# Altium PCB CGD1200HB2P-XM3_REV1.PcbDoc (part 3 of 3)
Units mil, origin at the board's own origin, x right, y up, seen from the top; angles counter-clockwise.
Board outline 2086.61 x 3149.61 mil, 6 copper layers (TOP, LAYER2, LAYER3, LAYER4, LAYER5, BOTTOM), stack 57.2 mil thick; 178 components, 101 nets, 513 pads, 419 vias.
Unrouted connection lines stored in the file: 206.
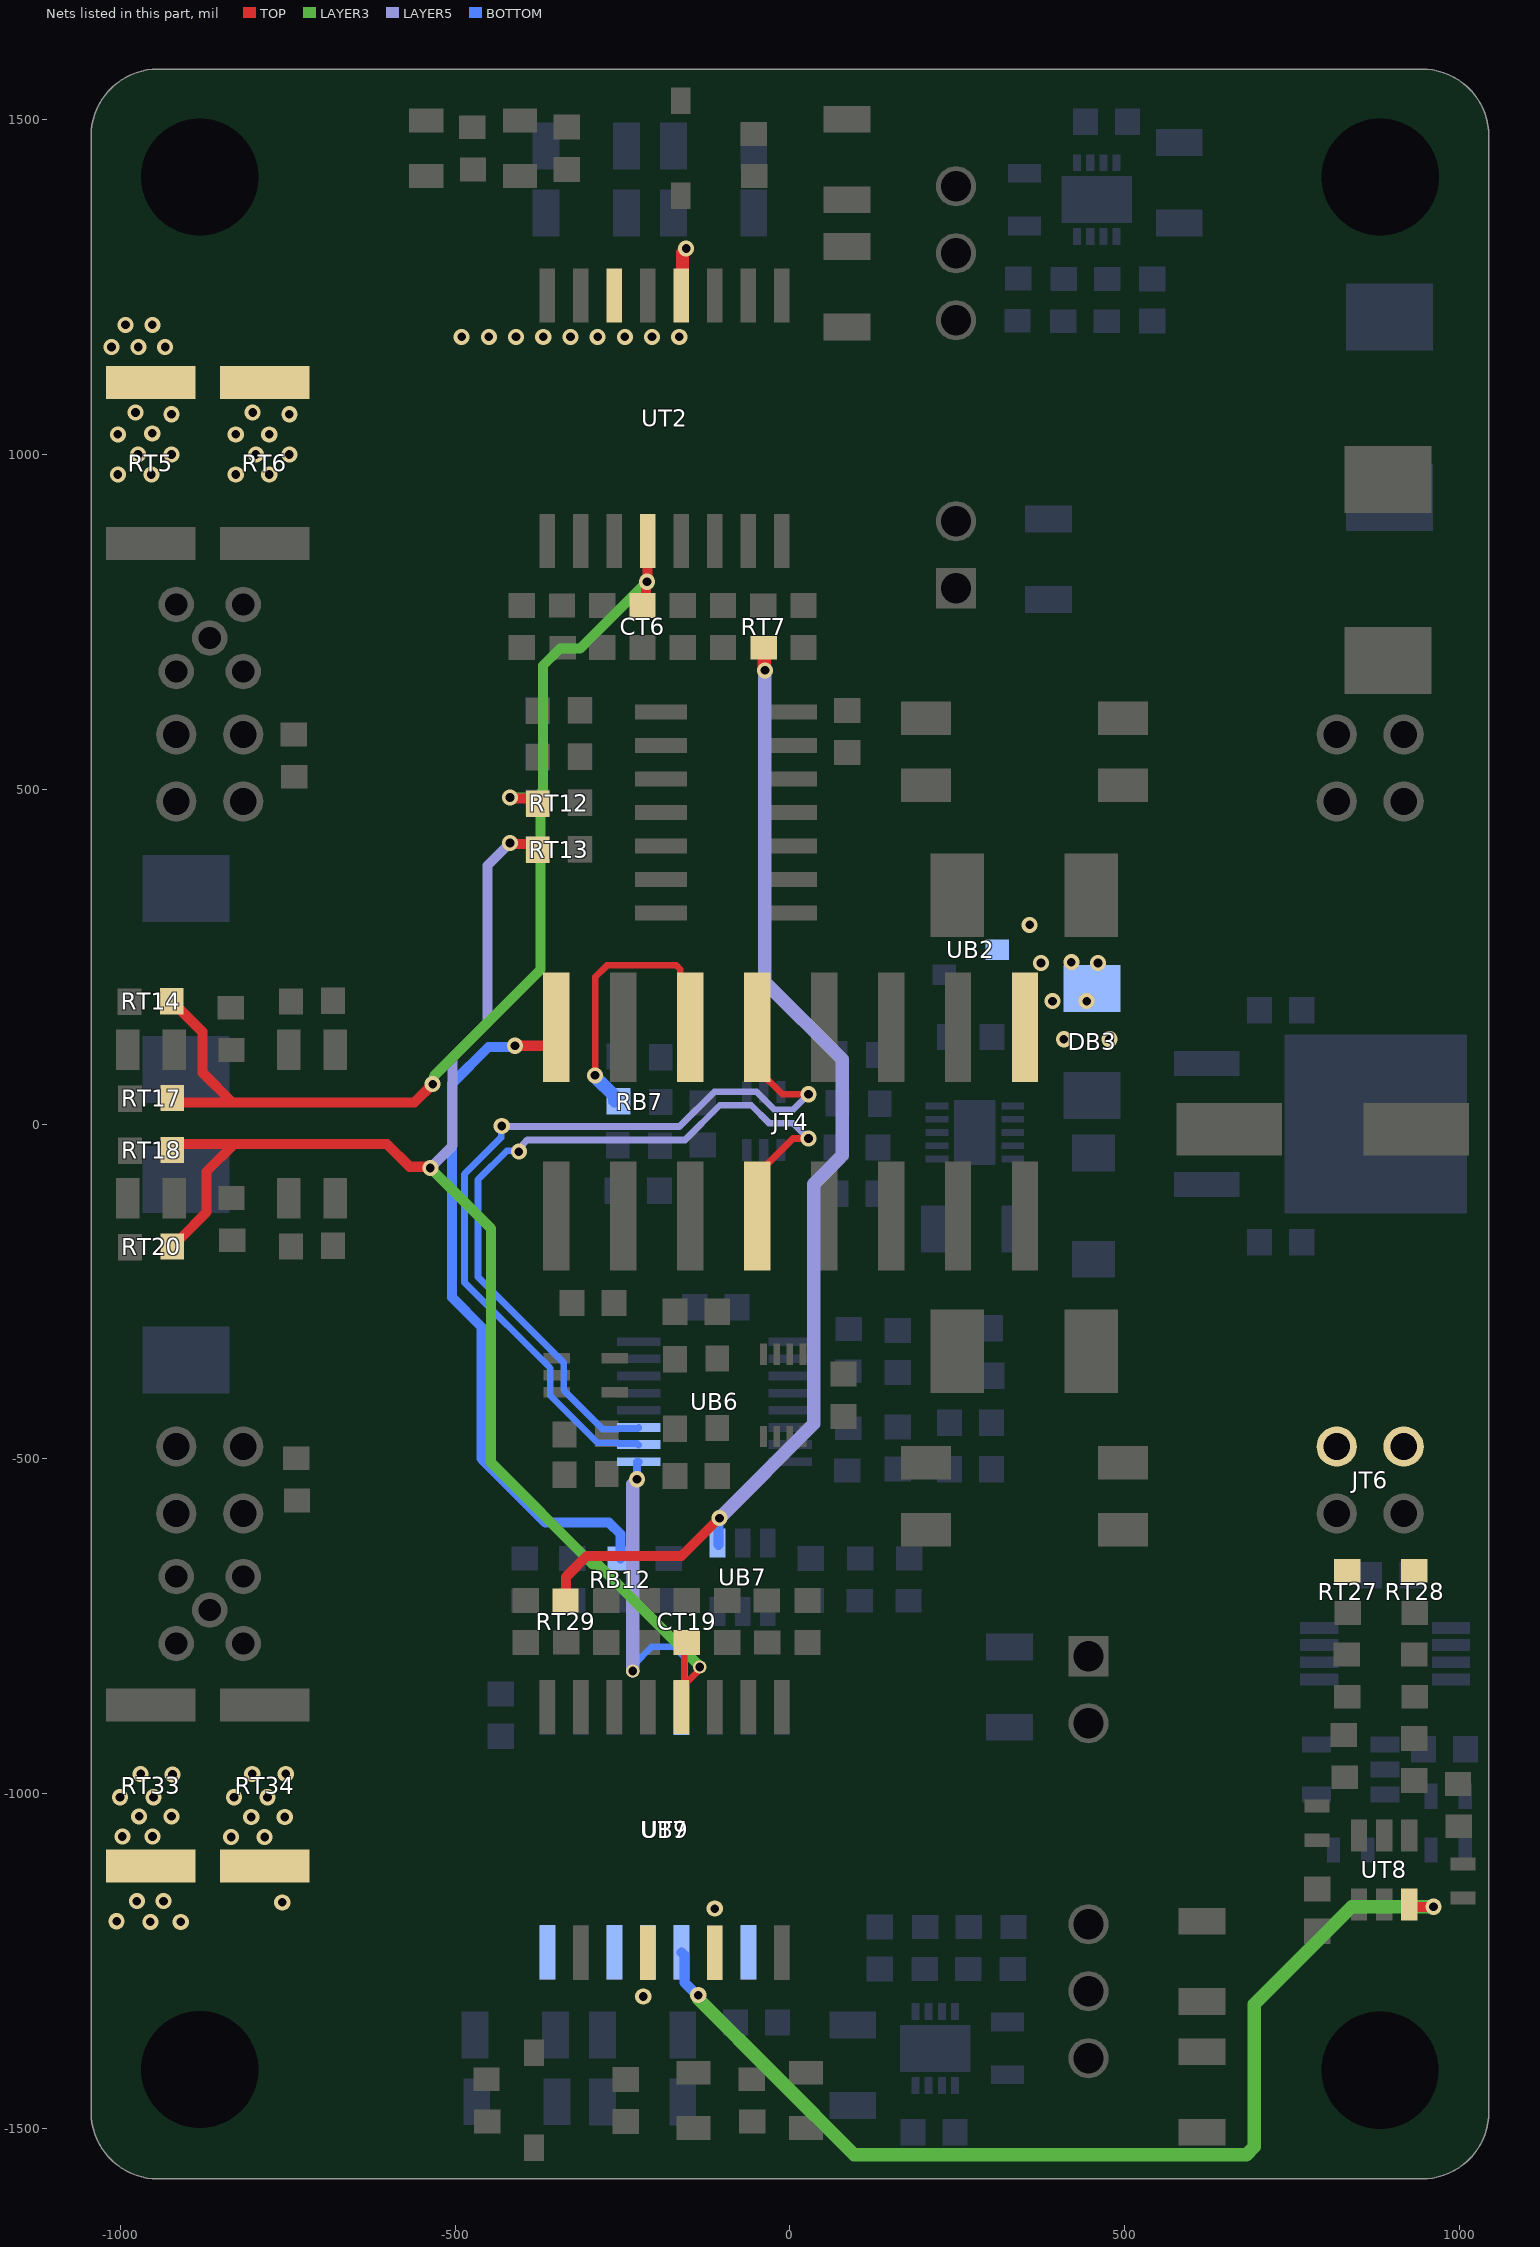
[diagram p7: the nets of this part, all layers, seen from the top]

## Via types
v1: diameter 24.02, hole 12.99, TOP to BOTTOM, tented both sides, 415 vias
v2: diameter 20, hole 12.99, TOP to BOTTOM, tented both sides, 4 vias

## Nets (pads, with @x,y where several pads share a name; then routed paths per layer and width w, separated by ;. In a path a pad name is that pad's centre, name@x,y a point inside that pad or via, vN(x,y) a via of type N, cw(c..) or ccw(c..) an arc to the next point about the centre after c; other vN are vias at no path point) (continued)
PS-DIS: JT4.11 RB7.2 | length 454
  TOP w10: v1(-291.13,72.61) -290.69,73.05 -290.69,219.43 -273.3,236.82 -169.6,236.82 -163.74,230.96 -163.74,131.25 JT4.11@-149.06,116.57
  BOTTOM w20: v1(-291.13,72.61) -290.37,71.84 -290.37,70.1 -261.5,41.24 RB7.2@-261.5,34.98
RDY_HS: CT6.1 RT12.1 RT14.2 RT17.2 UT2.4 | length 1683.7
  TOP w15: RT17.2@-922.28,38.76 -915.47,31.94 -832.01,31.94 ; RT14.2@-922.28,182.81 -922.28,180.98 -912.6,171.3 -910.77,171.3 -877.22,137.75 -877.22,77.16 -832.01,31.94 ; v1(-533.31,59.48) -560.85,31.94 -832.01,31.94 ; v1(-417.81,487.44) -416.08,485.71 -383.95,485.71 RT12.1@-376.56,478.32 ; CT6.1@-220.08,774.04 -215.04,779.08 -215.04,807.76 -212.66,810.14 -212.66,871.99 UT2.4@-212.03,872.61
  LAYER3 w15: v1(-533.31,59.48) -531.59,61.21 -531.59,71.21 -372.45,230.34 -372.45,481.35 -378.73,487.64 ; v1@-417.61,487.64 -378.73,487.64 ; v1(-213.31,809.48) -313.31,709.48 -343.31,709.48 -368.49,684.3 -368.49,497.88 -378.73,487.64
RDY_LS: CT19.1 RT13.1 RT18.2 RT20.2 UT7.4 | length 2242.4
  TOP w10: UT7.4@-157.97,-895.3 UT7.4@-157.97,-837.82 ; CT19.1@-153.93,-774.16 -157.97,-778.19 UT7.4@-157.97,-837.82 ; v2(-134.51,-810.52) -136.24,-812.24 -136.24,-816.09 UT7.4@-157.97,-837.82
  TOP w15: RT20.2@-922.28,-179.97 -913.05,-170.74 -909.89,-170.74 -870.82,-131.68 -870.82,-70.88 -830.01,-30.06 ; RT18.2@-922.28,-38.87 -913.47,-30.06 -830.01,-30.06 ; v1(-536.8,-65.57) -538.52,-63.84 -567.73,-63.84 -601.51,-30.06 -830.01,-30.06 ; v1@-410.52,419.48 -408.8,417.76 -385.05,417.76 RT13.1@-376.56,409.27
  LAYER3 w15: v1(-536.8,-65.57) -495.11,-107.25 -446,-156.36 -446,-505.78 -294.02,-657.76 -286.07,-657.76 -134.51,-809.31 v2(-134.51,-810.52)
  LAYER5 w15: v1(-536.8,-65.57) -503.56,-32.33 -503.56,99.23 -451.51,151.28 -451.51,385.78 v1(-417.81,419.48)
RESET: RT7.1 RT29.1 UB7.4 | length 1766.1
  TOP w15: RT29.1@-335.08,-711.16 -334.1,-711.16 -334.1,-675.95 -303.21,-645.06 -161.9,-645.06 v1(-105.15,-588.31)
  TOP w20: RT7.1@-38.93,711.05 -38.14,710.26 -38.14,677.93 v1(-37.37,677.17) v1@-37.37,674.69
  LAYER5 w20: v1(-105.15,-588.31) 35.49,-447.67 35.49,-89.57 74.99,-50.06 74.99,-49.66 77.99,-46.66 77.99,96.54 -37.45,211.99 -37.45,442.74 -37.37,442.82 v1@-37.37,674.69
  BOTTOM w15: UB7.4@-106.88,-628.52 -106.88,-590.03 v1(-105.15,-588.31)
"RESET INPUT": JT4.15 RB12.2 | length 1046.6
  TOP w15: v1(-410.34,116.81) -351.08,116.81 JT4.15@-350.19,117.7
  BOTTOM w15: v1(-410.34,116.81) -412.06,115.09 -449.87,115.09 -504.23,60.73 -504.23,-259.17 -460.51,-302.89 -460.51,-499.55 -365.01,-595.06 -270.01,-595.06 -252.99,-612.08 RB12.2@-252.99,-648.56
RTD: JT6.1 JT6.3 RT27.2 RT28.2
RTD-ISO: UB9.4 UT8.6 | length 1591
  TOP w15: UT8.6@924.35,-1163.52 924.35,-1163.81 929.05,-1168.51 v1(960.58,-1168.51)
  LAYER3 w20: v1(-136.83,-1300.41) -136.06,-1301.18 -136.06,-1306.62 -20.11,-1422.57 95.85,-1538.53 681.52,-1538.53 693.24,-1526.81 693.24,-1313.85 838.58,-1168.51 v1(960.58,-1168.51)
  BOTTOM w15: UB9.4@-162.01,-1236.54 -157.7,-1240.85 -157.7,-1281.27 -138.56,-1300.41 v1(-136.83,-1300.41)
RTD-NON-ISO: UB6.9 UB9.13 | length 497.2
  LAYER5 w20: v2(-234.51,-816.6) -234.51,-537.62 -228.23,-531.34 v1(-228.23,-530.25)
  BOTTOM w10: v2(-234.51,-816.6) -232.79,-814.88 -232.79,-806.76 -206.38,-780.35 -172.26,-780.35 -157.97,-794.65 -157.97,-867.15 UB9.13@-162.01,-871.18
  BOTTOM w12: v1(-228.23,-530.25) UB6.9@-228.23,-504.69 ; UB6.9@-228.2,-504.66 UB6.9@-226.02,-504.66
RTD-Output_N: JT4.10 UB6.11 | length 1229.8
  TOP w10: JT4.10@-49.06,-137.37 -49.06,-75.36 4.55,-21.75 v1(27.77,-21.75)
  LAYER5 w10: v1(-404.74,-41.29) -404.74,-37.5 -398.17,-30.92 -398.17,-29.67 -392.31,-23.81 -156.5,-23.81 -104.72,27.96 -57.86,27.96 -31.22,1.32 4.7,1.32 v1(27.77,-21.75)
  BOTTOM w10: v1(-404.74,-41.29) -406.06,-39.98 -422.59,-39.98 -465.73,-83.12 -465.73,-228.34 -337.85,-356.22 -337.85,-396.91 -278.98,-455.79 -257.38,-455.79 -256.08,-454.49 -227.08,-454.49 UB6.11@-225.58,-452.99
RTD-Output_P: JT4.9 UB6.10 | length 1267.9
  TOP w10: JT4.9@-49.06,116.57 -49.06,82.12 -11.33,44.39 v1(27.77,44.39)
  LAYER5 w10: v1(-430.18,-2.99) -429.35,-3.82 -403.7,-3.82 -164.78,-3.81 -113.01,47.96 -49.57,47.96 -22.93,21.32 4.7,21.32 v1(27.77,44.39)
  BOTTOM w10: v1(-430.18,-2.99) -431.13,-3.94 -431.13,-20.23 -485.73,-74.84 -485.73,-236.63 -357.85,-364.51 -357.85,-405.19 -287.26,-475.79 -257.38,-475.79 -256.08,-477.09 -227.99,-477.09 UB6.10@-226.02,-479.06
UB8NC1: UB9.2
UB8NC2: UB9.5
UB8NC3: UB9.6
UB8NC4: UB9.8
UNPROTECTED_VIN: DB3.C JT4.1 UB2.3
  other v1: 408.86,126.48 476.94,126.48 391.84,183.44 442.9,183.44 374.82,240.39 459.92,240.39 420.02,241.53 357.8,297.35
VOUT_OFF_HS: RT6.1 UT2.12 | length 73
  TOP w20: UT2.12@-162.03,1236.84 -160.39,1238.48 -160.39,1300.46 -155,1305.85 v1(-155,1306.93)
  other v1: -827.25,969.48 -777.25,969.48 -797.25,999.48 -747.25,999.48 -827.25,1029.48 -777.25,1029.48 -747.25,1059.48 -802,1062 -490,1175 -449.41,1175 -408.81,1175 -368.22,1175 -327.63,1175 -287.03,1175 -246.44,1175 -205.85,1175 -165.26,1175
VOUT_OFF_LS: RT33.1 UT7.12
  other v1: -219.06,-1302.52 -1005,-1190.05 -954.72,-1190.94 -909.45,-1190.94 -975,-1160.05 -935,-1160.05 -996.57,-1063.58 -951.46,-1063.46 -971.46,-1033.46 -923.32,-1033.46 -1000,-1005.05 -950,-1005.05 -969.22,-970.05 -921.75,-970.93
VOUT_ON_HS: RT5.1 UT2.14
  other v1: -1003.31,969.48 -953.31,969.48 -973.31,999.48 -923.31,999.48 -1003.31,1029.48 -952,1031 -923.31,1059.48 -977,1062 -1012.76,1159.96 -972.76,1159.96 -932.76,1159.96 -991.77,1192.91 -951.77,1192.91
VOUT_ON_LS: RT34.1 UT7.14
  other v1: -112.2,-1171.26 -757.88,-1161.93 -834.13,-1064.45 -784.13,-1064.45 -804.13,-1034.45 -754.13,-1034.45 -830,-1005.05 -780,-1005.05 -802.68,-970.05 -752.68,-970.05
pads on no net: M1.1 M2.1 M3.1 M4.1 UB4.3 UB4.4 UB5.5 UB9.10 UB9.11 UB9.12 UB9.15 UB10.1 UB10.2 UT3.3 UT3.8 UT3.11

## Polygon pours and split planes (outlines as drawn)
0 on LAYER2 "LAYER2-0" (solid, remove dead copper, pour order 1145): 82 vertices, not listed, extent -1033.31,-1565.61 1033.31,1564
LS-SOURCE on LAYER2 "LAYER2-LS-SOURCE" (solid, remove dead copper, pour order 1144): 51 vertices, not listed, extent -1035.31,-1565 1031.31,-439.14
HS-SOURCE on LAYER2 "LAYER2-HS-SOURCE" (solid, remove dead copper, pour order 1143): 79 vertices, not listed, extent -1031.97,428.17 1034.65,1569.75
NetDB1_C on LAYER2 "LAYER2-N6026743" (solid, remove dead copper, pour order 1148): 757.02,875.74 ccw(c782.87,875.74) 782.87,849.89 1007.93,849.89 ccw(c1008.16,874.18) 1032.45,873.95 1032.45,991.64 ccw(c1009.15,991.64) 1009.15,1014.94 782.02,1014.94 ccw(c782.02,989.94) 757.02,989.94
HS-DRAIN on LAYER2 "LAYER2-HS-DRAIN" (solid, remove dead copper, pour order 1130): 82 vertices, not listed, extent 757.87,423.17 1033.3,754.94
"Gate Sense LS" on TOP "TOP-LS-GATE" (solid, remove dead copper, pour order 1141): -1037.92,-463.71 cw(c-1017.13,-463.71) -1017.13,-442.91 -722.02,-442.91 cw(c-722.02,-465.32) -699.62,-465.32 -699.62,-894.66 cw(c-710,-894.66) -710,-905.05 -1025,-905.05 cw(c-1025,-892.13) -1037.92,-892.13
"Gate Sense HS" on TOP "TOP-HS-GATE" (solid, remove dead copper, pour order 1140): -732.31,906.48 cw(c-732.31,875.48) -701.31,875.48 -701.31,457.48 cw(c-717.31,457.48) -717.31,441.48 -1014.31,441.48 cw(c-1013.81,460.98) -1033.31,461.48 -1033.31,881.48 cw(c-1008.31,881.48) -1008.31,906.48
RTD on TOP "TOP-RTD2" (solid, remove dead copper, pour order 1125): 765.08,-475.88 cw(c800.94,-475.88) 800.94,-440.02 915.25,-440.02 1001.6,-440.02 cw(c1001.61,-476.8) 1038.39,-476.8 1038.39,-660.04 cw(c1006.41,-660.68) 1010.24,-692.43 803.52,-692.43 cw(c803.52,-653.99) 765.08,-653.99 765.08,-623.41
-5V_LS on TOP "TOP--5V_LS" (solid, remove dead copper, pour order 1136): 33 vertices, not listed, extent 114.99,-1535.06 659.99,-1153.88
HS-VDD on TOP "TOP-HS-VDD" (solid, remove dead copper, pour order 1094): 122 vertices, not listed, extent 37.15,1352.44 297.15,1532.44
LS-VDD on TOP "TOP-LS-VDD" (solid, remove dead copper, pour order 1092): 81 vertices, not listed, extent 384,-1535.06 659.99,-1359.86
VOUT_ON_HS on TOP "TOP-VOUT_ON_HS" (solid, remove dead copper, pour order 1137): 83 vertices, not listed, extent -1033.31,919.96 -235.01,1347.3
5V on TOP "TOP-5V 1" (solid, remove dead copper, pour order 1135): 127 vertices, not listed, extent -1033.31,-223.29 -451.51,223.17
VOUT_OFF_LS on TOP "TOP-VOUT_OFF_LS" (solid, remove dead copper, pour order 1134): 89 vertices, not listed, extent -1033.31,-1344.5 -195.01,-920.05
VOUT_OFF_HS on TOP "TOP-VOUT_OFF_HS" (solid, remove dead copper, pour order 1126): 69 vertices, not listed, extent -863.06,919.95 -135.01,1279.94
VOUT_ON_LS on TOP "TOP-VOUT_ON_LS" (solid, remove dead copper, pour order 1124): 89 vertices, not listed, extent -862.31,-1276.43 -85.01,-920.05
0 on TOP "TOP-0 3" (solid, remove dead copper, pour order 1081): 95 vertices, not listed, extent -1033.31,-148.24 -494.14,148.13
12V_SWITCHED on TOP "TOP-12V_SWITCHED" (solid, remove dead copper, pour order 1080): 75 vertices, not listed, extent 204.99,25.54 399.99,407.25
LS-VDD on TOP "TOP-LS-VDD 1" (solid, remove dead copper, pour order 1064): 80 vertices, not listed, extent -215.01,-1395.06 -95.01,-1197.43
NetDB1_C on TOP "TOP-N6026743" (solid, remove dead copper, pour order 1152): 757.87,875.74 ccw(c783.72,875.74) 783.72,849.89 1008.78,849.89 ccw(c1009.01,874.18) 1033.3,873.95 1033.3,991.64 ccw(c1010,991.64) 1010,1014.94 782.87,1014.94 ccw(c782.87,989.94) 757.87,989.94
NetCB8_2 on TOP "TOP-N5777737" (solid, remove dead copper, pour order 1090): 101 vertices, not listed, extent 153.93,559.94 319.99,939.56
NetCB28_1 on TOP "TOP-N5778706" (solid, remove dead copper, pour order 1100): 84 vertices, not listed, extent 369.99,-845.86 546.06,-465.86
NetCB8_1 on TOP "TOP-N5777665" (solid, remove dead copper, pour order 1096): 146 vertices, not listed, extent 153.93,465.75 319.99,845.75
NetCB28_2 on TOP "TOP-N5778794" (solid, remove dead copper, pour order 1093): 101 vertices, not listed, extent 369.99,-933.36 546.06,-560.06
LS-SOURCE on TOP "TOP-LS-SOURCE" (solid, remove dead copper, pour order 1082): 122 vertices, not listed, extent 374.99,-1420.06 659.99,-1253.86
HS-SOURCE on TOP "TOP-HS-SOURCE" (solid, remove dead copper, pour order 1079): 122 vertices, not listed, extent 39.99,1255.75 299.99,1419.94
-5V_HS on TOP "TOP--5V_HS" (solid, remove dead copper, pour order 1074): 82 vertices, not listed, extent 39.99,1153.75 299.99,1243.75
0 on TOP "TOP-0 1" (solid, remove dead copper, pour order 1086): -129.32,-75.21 -129.32,-224.81 -368.69,-224.81 -368.69,-75.21 -129.32,-75.21
NetFT1_2 on TOP "TOP-N5143626" (solid, remove dead copper, pour order 1095): 105 vertices, not listed, extent 394.99,277.25 552.87,555.75
NetFT2_2 on TOP "TOP-N5780153" (solid, remove dead copper, pour order 1085): 63 vertices, not listed, extent 150.24,-556.98 294.99,-267.36
0 on TOP "TOP-0" (solid, remove dead copper, pour order 1063): 82 vertices, not listed, extent 413.99,569.94 551.87,639.94
0 on TOP "TOP-0 2" (solid, remove dead copper, pour order 1062): 82 vertices, not listed, extent 150.24,-640.06 279.99,-570.06
0 on TOP "TOP-0 4" (solid, remove dead copper, pour order 1138): 764.99,204.72 cw(c779.76,204.72) 779.76,219.49 1013.62,219.49 cw(c1013.62,199.8) 1033.3,199.8 1033.3,-205.83 cw(c1019.42,-205.83) 1019.42,-219.72 778.02,-219.72 cw(c778.02,-206.69) 764.99,-206.69
HS-DRAIN on TOP "TOP-HS-DRAIN" (solid, remove dead copper, pour order 1129): 82 vertices, not listed, extent 757.87,423.17 1033.3,754.94
12V on TOP "TOP-12V" (solid, remove dead copper, pour order 1102): 43 vertices, not listed, extent 557.95,-217.52 752.95,33.56
12V_SWITCHED on TOP "TOP-12V_SWITCHED 1" (solid, remove dead copper, pour order 1091): 40 vertices, not listed, extent 404.99,-436.47 694.72,-233.29
5V on TOP "TOP-5V" (solid, remove dead copper, pour order 1089): 43 vertices, not listed, extent 559.54,41.85 754.54,221.39
UNPROTECTED_VIN on TOP "TOP-UNPROTECTED_VIN" (solid, remove dead copper, pour order 1087): 82 vertices, not listed, extent 326.31,50.22 489.31,335.94
LS-VSS on TOP "TOP-LS-VSS" (solid, remove dead copper, pour order 1069): 64 vertices, not listed, extent -30.01,-1288.06 249.99,-1153.97
no net on Top Overlay "NONET_L-01_P-001" (solid): 561.31,1574.65 1043.29,1092.67 1043.31,1474.75 ccw(c943.3,1474.75) 943.3,1574.76
VOUT_ON_LS on BOTTOM "BOTTOM-VOUT_ON_LS" (solid, remove dead copper, pour order 1150): 36 vertices, not listed, extent -862.31,-1230.06 -85.01,-920.05
LS-VSS on BOTTOM "BOTTOM-LS-VSS" (solid, pour order 1123): 145 vertices, not listed, extent -50.06,-1375.06 362.55,-1153.86
LS-VDD on BOTTOM "BOTTOM-LS-VDD" (solid, pour order 1133): 132 vertices, not listed, extent -219.01,-1564.86 660.99,-1320.12
12V on BOTTOM "BOTTOM-12V 1" (solid, remove dead copper, pour order 1120): 150 vertices, not listed, extent 135.99,-74.86 342.02,324.94
0 on BOTTOM "BOTTOM-0" (solid, remove dead copper, pour order 1098): 100 vertices, not listed, extent 30.99,-258.06 250.99,-18.06
-5V_LS on BOTTOM "BOTTOM--5V_LS 1" (solid, remove dead copper, pour order 1077): 107 vertices, not listed, extent 163.79,-1534.74 362.55,-1345.06
-5V_HS on BOTTOM "BOTTOM--5V_HS 1" (solid, remove dead copper, pour order 1076): 51 vertices, not listed, extent 312.44,1344.94 511.19,1534.63
HS-VSS on BOTTOM "BOTTOM-HS-VSS 1" (solid, remove dead copper, pour order 1061): 145 vertices, not listed, extent 313.6,1153.75 629.99,1373.15
HS-VDD on BOTTOM "BOTTOM-HS-VDD" (solid, remove dead copper, pour order 1142): 143 vertices, not listed, extent -605.01,1244.94 299.99,1559.94
HS-SOURCE on BOTTOM "BOTTOM-HS-SOURCE" (solid, remove dead copper, pour order 1127): 222 vertices, not listed, extent -275.01,1153.75 371.16,1494.94
12V_SWITCHED on BOTTOM "BOTTOM-12V_SWITCHED" (solid, remove dead copper, pour order 1122): 147 vertices, not listed, extent 299.99,-436.47 667.67,50.22
NetDB1_C on BOTTOM "LAYER5-N6026743" (solid, remove dead copper, pour order 1154): 757.87,875.74 ccw(c783.72,875.74) 783.72,849.89 1008.78,849.89 ccw(c1009.01,874.18) 1033.3,873.95 1033.3,991.64 ccw(c1010,991.64) 1010,1014.94 782.87,1014.94 ccw(c782.87,989.94) 757.87,989.94
0 on BOTTOM "BOTTOM-0 2" (solid, remove dead copper, pour order 1065): 421.18,-134.84 ccw(c421.17,-140.01) 416,-139.99 416,-231 ccw(c419.01,-231) 419.01,-234.01 488.05,-233.93 ccw(c488.06,-231) 491,-231.01 491,-140 ccw(c485.84,-140) 485.84,-134.84
NetCB28_2 on BOTTOM "BOTTOM-N5778794" (solid, remove dead copper, pour order 1070): 43 vertices, not listed, extent 280.24,-933.37 499.99,-854.86
VOUT_OFF_HS on BOTTOM "BOTTOM-VOUT_OFF_HS" (solid, remove dead copper, pour order 1149): 19 vertices, not listed, extent -863.06,919.95 -145.04,1269.94
UNPROTECTED_VIN on BOTTOM "BOTTOM-UNPROTECTED_VIN" (solid, remove dead copper, pour order 1097): 105 vertices, not listed, extent 294.79,114.72 494.61,324.72
LS-SOURCE on BOTTOM "BOTTOM-LS-SOURCE 2" (solid, remove dead copper, pour order 1099): 185 vertices, not listed, extent 298.09,-1420.06 653.09,-1153.86
-5V_LS on BOTTOM "BOTTOM--5V_LS" (solid, remove dead copper, pour order 1075): 27 vertices, not listed, extent 400.07,-1243.86 659.99,-1153.85
-5V_HS on BOTTOM "BOTTOM--5V_HS" (solid, remove dead copper, pour order 1073): 39.99,1172.39 39.99,1169.63 ccw(c53.24,1169.63) 53.24,1156.38 276.29,1156.38 ccw(c276.29,1170.09) 289.99,1170.09 289.99,1228.83 ccw(c275.08,1228.83) 275.08,1243.75 268.94,1243.75 54.45,1243.75 ccw(c53.71,1230.03) 39.99,1230.77
NetCB8_2 on BOTTOM "BOTTOM-N5777737" (solid, pour order 1072): 44 vertices, not listed, extent 199.99,854.75 434.99,939.76
NetCB8_1 on BOTTOM "BOTTOM-N5777665" (solid, remove dead copper, pour order 1071): 82 vertices, not listed, extent 199.99,749.75 434.99,844.75
NetCB28_1 on BOTTOM "BOTTOM-N5778706" (solid, remove dead copper, pour order 1068): 82 vertices, not listed, extent 280.24,-844.86 499.99,-749.86
0 on BOTTOM "BOTTOM-0 1" (solid, remove dead copper, pour order 1139): 43 vertices, not listed, extent 730.72,-228.41 1015.73,219.49
LS-SOURCE on BOTTOM "BOTTOM-LS-SOURCE" (solid, remove dead copper, pour order 1121): -410.01,-1286.43 -220.01,-1286.43 -220.01,-1564.86 -410.01,-1564.86 -410.01,-1286.43
LS-SOURCE on BOTTOM "BOTTOM-LS-SOURCE 1" (solid, remove dead copper, pour order 1078): 89 vertices, not listed, extent -100.2,-1536.17 209.32,-1331.06
HS-VSS on BOTTOM "BOTTOM-HS-VSS" (solid, remove dead copper, pour order 1083): 82 vertices, not listed, extent -135.01,1324.94 29.99,1494.94
NetDB2_A on BOTTOM "BOTTOM-N6026743" (solid, remove dead copper, pour order 1146): 44 vertices, not listed, extent -979.5,-150.06 -824.5,151.48
LS-VSS on BOTTOM "BOTTOM-LS-VSS 1" (solid, remove dead copper, pour order 1119): -410.01,-1564.86 -575.01,-1564.86 -575.01,-1286.43 -410.01,-1286.43 -410.01,-1564.86
12V on BOTTOM "BOTTOM-12V" (solid, remove dead copper, pour order 1088): 82 vertices, not listed, extent 541.49,-223.29 720.29,-35.06
5V on BOTTOM "BOTTOM-5V" (solid, remove dead copper, pour order 1084): 44 vertices, not listed, extent 541.49,34.94 720.29,218.5
HS-SOURCE on BOTTOM "BOTTOM-HS-SOURCE 1" (solid, remove dead copper, pour order 1067): 44 vertices, not listed, extent 469.99,1422.5 629.99,1534.63
NetDB3_A on BOTTOM "BOTTOM-N5927082" (solid, remove dead copper, pour order 1066): 82 vertices, not listed, extent 407.31,-88.95 493.31,86.05
5V on LAYER4 "LAYER4-5V" (solid, remove dead copper, pour order 1118): 82 vertices, not listed, extent -1030.68,-1569.16 1035.93,1560.45
HS-VDD on LAYER4 "LAYER4-HS-VDD" (solid, remove dead copper, pour order 1113): 43 vertices, not listed, extent -1033.31,419.29 1033.3,1564.4
LS-VDD on LAYER4 "LAYER4-LS-VDD" (solid, remove dead copper, pour order 1111): 49 vertices, not listed, extent -1033.31,-1564.86 1033.3,-439
"Gate Sense HS" on LAYER4 "Gate Sense HS" (solid, remove dead copper, pour order 1108): -949.05,419.95 cw(c-949.05,434.95) -964.05,434.95 -964.05,799.95 cw(c-944.05,799.95) -944.05,819.95 -788.24,819.95 cw(c-788.24,794.62) -762.91,794.62 -762.91,446.1 cw(c-789.05,446.1) -789.05,419.95
"Gate Sense LS" on LAYER4 "Gate Sense LS" (solid, remove dead copper, pour order 1106): -942.21,-840.05 cw(c-942.21,-814.34) -967.91,-814.34 -967.91,-467.95 cw(c-940,-467.95) -940,-440.05 -792.1,-440.05 cw(c-792.1,-465.38) -766.77,-465.38 -766.77,-813.9 cw(c-792.91,-813.9) -792.91,-840.05
0 on LAYER4 "LAYER4-0" (solid, remove dead copper, pour order 1103): 764.99,-203.97 ccw(c783.46,-203.97) 783.46,-222.44 1013.91,-222.44 ccw(c1013.79,-202.93) 1033.3,-202.81 1033.3,196.03 ccw(c1009.85,196.03) 1009.84,219.49 787.4,219.49 ccw(c787.51,196.97) 764.99,196.85
NetDB1_C on LAYER4 "LAYER4-N6026743" (solid, remove dead copper, pour order 1117): 757.02,875.74 ccw(c782.87,875.74) 782.87,849.89 1007.93,849.89 ccw(c1008.16,874.18) 1032.45,873.95 1032.45,991.64 ccw(c1009.15,991.64) 1009.15,1014.94 782.02,1014.94 ccw(c782.02,989.94) 757.02,989.94
HS-DRAIN on LAYER4 "LAYER4-HS-DRAIN" (solid, remove dead copper, pour order 1116): 82 vertices, not listed, extent 757.87,423.17 1033.3,754.94
0 on LAYER5 "LAYER5-0" (solid, pour order 1115): 43 vertices, not listed, extent -1030.68,-1564.53 1033.3,1565.08
LS-VSS on LAYER5 "LAYER5-LS-VSS" (solid, remove dead copper, pour order 1112): 52 vertices, not listed, extent -1033.31,-1564.86 1033.3,-439
HS-VSS on LAYER5 "LAYER5-HS-VSS" (solid, remove dead copper, pour order 1110): 79 vertices, not listed, extent -1033.31,423.17 1033.3,1564.75
LS-SOURCE on LAYER5 "LS-SOURCE" (solid, remove dead copper, pour order 1107): -948.96,-840.05 cw(c-948.96,-825.05) -963.96,-825.05 -963.96,-460.05 cw(c-943.96,-460.05) -943.96,-440.05 -788.15,-440.05 cw(c-788.15,-465.38) -762.82,-465.38 -762.82,-813.9 cw(c-788.96,-813.9) -788.96,-840.05
HS-SOURCE on LAYER5 "HS-SOURCE" (solid, remove dead copper, pour order 1105): -966.15,446.46 ccw(c-942.91,446.46) -942.91,423.23 -791.83,423.23 ccw(c-791.37,449.59) -765,449.13 -765,804.95 ccw(c-780,804.96) -780,819.95 -940,819.95 ccw(c-940,793.81) -966.15,793.81
12V on LAYER5 "12V_L05_P1104" (solid, remove dead copper, pour order 1104): 573.19,326.99 640.93,259.25 ccw(c734.36,359.29) 737.69,222.44 737.69,-224.27 ccw(c735.18,-388.76) 613.6,-277.93 590.29,-303.51 572.69,-303.01 122.61,-303.01 122.61,326.99
NetDB1_C on LAYER5 "LAYER5-N6026743" (solid, remove dead copper, pour order 1114): 757.02,875.74 ccw(c782.87,875.74) 782.87,849.89 1007.93,849.89 ccw(c1008.16,874.18) 1032.45,873.95 1032.45,991.64 ccw(c1009.15,991.64) 1009.15,1014.94 782.02,1014.94 ccw(c782.02,989.94) 757.02,989.94
HS-DRAIN on LAYER5 "LAYER5-HS-DRAIN" (solid, remove dead copper, pour order 1109): 82 vertices, not listed, extent 757.87,423.17 1033.3,754.94
VOUT_OFF_LS on LAYER3 "LAYER3-VOUT_OFF_LS" (solid, remove dead copper, pour order 1151): 50 vertices, not listed, extent -1034,-1344.5 -195.69,-920.05
VOUT_ON_HS on LAYER3 "VOUT_ON_HS" (solid, remove dead copper, pour order 1147): 90 vertices, not listed, extent -1033.31,919.96 -235.03,1361.03
-5V_LS on LAYER3 "LAYER3--5V_LS" (solid, remove dead copper, pour order 1132): 56 vertices, not listed, extent 129.99,-1522.23 715.12,-1153.83
-5V_HS on LAYER3 "LAYER3--5V_HS" (solid, remove dead copper, pour order 1131): 122 vertices, not listed, extent 49.99,1153.75 514.99,1529.75
NetDB1_C on LAYER3 "LAYER3-N6026743" (solid, remove dead copper, pour order 1153): 757.87,875.74 ccw(c783.72,875.74) 783.72,849.89 1008.78,849.89 ccw(c1009.01,874.18) 1033.3,873.95 1033.3,991.64 ccw(c1010,991.64) 1010,1014.94 782.87,1014.94 ccw(c782.87,989.94) 757.87,989.94
HS-DRAIN on LAYER3 "LAYER3-HS-DRAIN" (solid, remove dead copper, pour order 1128): 82 vertices, not listed, extent 757.87,423.17 1033.3,754.94

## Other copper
TOP:
  pour cut-out: 880.9,1254.88 cw(c880.9,1412.36) 723.42,1412.36 cw(c880.9,1412.36) 880.9,1569.84 cw(c880.9,1412.36) 1038.38,1412.36 cw(c880.9,1412.36)
  pour cut-out: -816.15,642.24 cw(c-816.15,675.48) -849.38,675.48 cw(c-816.15,675.48) -816.15,708.72 cw(c-816.15,675.48) -782.91,675.48 cw(c-816.15,675.48)
  pour cut-out: -866.15,692.24 cw(c-866.15,725.48) -899.38,725.48 cw(c-866.15,725.48) -866.15,758.72 cw(c-866.15,725.48) -832.91,725.48 cw(c-866.15,725.48)
  pour cut-out: -816.15,742.24 cw(c-816.15,775.48) -849.38,775.48 cw(c-816.15,775.48) -816.15,808.72 cw(c-816.15,775.48) -782.91,775.48 cw(c-816.15,775.48)
  pour cut-out: -916.15,742.24 cw(c-916.15,775.48) -949.38,775.48 cw(c-916.15,775.48) -916.15,808.72 cw(c-916.15,775.48) -882.91,775.48 cw(c-916.15,775.48)
  pour cut-out: -916.15,642.24 cw(c-916.15,675.48) -949.38,675.48 cw(c-916.15,675.48) -916.15,708.72 cw(c-916.15,675.48) -882.91,675.48 cw(c-916.15,675.48)
  pour cut-out: -816.15,-808.8 cw(c-816.15,-775.56) -849.38,-775.56 cw(c-816.15,-775.56) -816.15,-742.32 cw(c-816.15,-775.56) -782.91,-775.56 cw(c-816.15,-775.56)
  pour cut-out: -866.15,-758.8 cw(c-866.15,-725.56) -899.38,-725.56 cw(c-866.15,-725.56) -866.15,-692.32 cw(c-866.15,-725.56) -832.91,-725.56 cw(c-866.15,-725.56)
  pour cut-out: -816.15,-708.8 cw(c-816.15,-675.56) -849.38,-675.56 cw(c-816.15,-675.56) -816.15,-642.32 cw(c-816.15,-675.56) -782.91,-675.56 cw(c-816.15,-675.56)
  pour cut-out: -916.15,-708.8 cw(c-916.15,-675.56) -949.38,-675.56 cw(c-916.15,-675.56) -916.15,-642.32 cw(c-916.15,-675.56) -882.91,-675.56 cw(c-916.15,-675.56)
  pour cut-out: -916.15,-808.8 cw(c-916.15,-775.56) -949.38,-775.56 cw(c-916.15,-775.56) -916.15,-742.32 cw(c-916.15,-775.56) -882.91,-775.56 cw(c-916.15,-775.56)
LAYER2:
  pour cut-out: 880.76,1256 cw(c880.76,1413.48) 723.28,1413.48 cw(c880.76,1413.48) 880.76,1570.96 cw(c880.76,1413.48) 1038.24,1413.48 cw(c880.76,1413.48)
  pour cut-out: -816.15,-808.8 cw(c-816.15,-775.56) -849.38,-775.56 cw(c-816.15,-775.56) -816.15,-742.32 cw(c-816.15,-775.56) -782.91,-775.56 cw(c-816.15,-775.56)
  pour cut-out: -866.15,-758.8 cw(c-866.15,-725.56) -899.38,-725.56 cw(c-866.15,-725.56) -866.15,-692.32 cw(c-866.15,-725.56) -832.91,-725.56 cw(c-866.15,-725.56)
  pour cut-out: -816.15,-708.8 cw(c-816.15,-675.56) -849.38,-675.56 cw(c-816.15,-675.56) -816.15,-642.32 cw(c-816.15,-675.56) -782.91,-675.56 cw(c-816.15,-675.56)
  pour cut-out: -916.15,-708.8 cw(c-916.15,-675.56) -949.38,-675.56 cw(c-916.15,-675.56) -916.15,-642.32 cw(c-916.15,-675.56) -882.91,-675.56 cw(c-916.15,-675.56)
  pour cut-out: -916.15,-808.8 cw(c-916.15,-775.56) -949.38,-775.56 cw(c-916.15,-775.56) -916.15,-742.32 cw(c-916.15,-775.56) -882.91,-775.56 cw(c-916.15,-775.56)
  pour cut-out: -916.15,642.24 cw(c-916.15,675.48) -949.38,675.48 cw(c-916.15,675.48) -916.15,708.72 cw(c-916.15,675.48) -882.91,675.48 cw(c-916.15,675.48)
  pour cut-out: -916.15,742.24 cw(c-916.15,775.48) -949.38,775.48 cw(c-916.15,775.48) -916.15,808.72 cw(c-916.15,775.48) -882.91,775.48 cw(c-916.15,775.48)
  pour cut-out: -816.15,742.24 cw(c-816.15,775.48) -849.38,775.48 cw(c-816.15,775.48) -816.15,808.72 cw(c-816.15,775.48) -782.91,775.48 cw(c-816.15,775.48)
  pour cut-out: -866.15,692.24 cw(c-866.15,725.48) -899.38,725.48 cw(c-866.15,725.48) -866.15,758.72 cw(c-866.15,725.48) -832.91,725.48 cw(c-866.15,725.48)
  pour cut-out: -816.15,642.24 cw(c-816.15,675.48) -849.38,675.48 cw(c-816.15,675.48) -816.15,708.72 cw(c-816.15,675.48) -782.91,675.48 cw(c-816.15,675.48)
LAYER3:
  pour cut-out: 880.9,1254.88 cw(c880.9,1412.36) 723.42,1412.36 cw(c880.9,1412.36) 880.9,1569.84 cw(c880.9,1412.36) 1038.38,1412.36 cw(c880.9,1412.36)
LAYER4:
  pour cut-out: 880.9,1254.88 cw(c880.9,1412.36) 723.42,1412.36 cw(c880.9,1412.36) 880.9,1569.84 cw(c880.9,1412.36) 1038.38,1412.36 cw(c880.9,1412.36)
LAYER5:
  pour cut-out: 880.76,1256 cw(c880.76,1413.48) 723.28,1413.48 cw(c880.76,1413.48) 880.76,1570.96 cw(c880.76,1413.48) 1038.24,1413.48 cw(c880.76,1413.48)
BOTTOM:
  pour cut-out: 880.76,1256 cw(c880.76,1413.48) 723.28,1413.48 cw(c880.76,1413.48) 880.76,1570.96 cw(c880.76,1413.48) 1038.24,1413.48 cw(c880.76,1413.48)
Multi-Layer:
  pour cut-out: 545,-932 545,-422.39 cw(c745,-422.39) 745,-222.39 1039.18,-222.39 1039.57,-439.41 754.06,-439.41 754.06,-1152.53 -695.94,-1152.47 -695.94,-446.9 ccw(c-766.86,-443.15) -695.94,-439.41 -854.55,-439.41 -1033.63,-438.17 -1033.63,-421.9 -1034.25,-421.9 -1034.25,-221.9 -715.94,-221.9 -697.7,-221.9 cw(c-697.69,-438.65) -480.94,-438.66 -480.94,-932
  pour cut-out: 546.73,939.17 546.73,421.95 ccw(c745.19,421.69) 744.93,223.23 1041.45,223.23 1043.15,223.23 1043.43,424.95 763.43,424.95 763.43,1161.63 -688.27,1161.63 -688.27,421.26 -1028.27,421.26 -1028.27,221.26 -678.74,221.26 ccw(c-678.74,426.73) -473.27,426.73 -473.27,939.17
  pour cut-out: -880.91,-1569.93 cw(c-880.91,-1412.45) -1038.39,-1412.45 cw(c-880.91,-1412.45) -880.91,-1254.97 cw(c-880.91,-1412.45) -723.43,-1412.45 cw(c-880.91,-1412.45)
  pour cut-out: 880.9,-1569.93 cw(c880.9,-1412.45) 723.42,-1412.45 cw(c880.9,-1412.45) 880.9,-1254.97 cw(c880.9,-1412.45) 1038.38,-1412.45 cw(c880.9,-1412.45)
  pour cut-out: -880.91,1254.88 cw(c-880.91,1412.36) -1038.39,1412.36 cw(c-880.91,1412.36) -880.91,1569.84 cw(c-880.91,1412.36) -723.43,1412.36 cw(c-880.91,1412.36)

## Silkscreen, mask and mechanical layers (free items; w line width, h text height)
Top Overlay:
  drawing of 46 lines, arcs and shapes, not listed
  text "ON" at -675,1130 h60
  text "OFF" at -675,974.95 h60
  text "REV1" at 725,629.98 h80 r90
  text "G1" at -1024.99,614.95 h30
  text "V+" at 702.8,514.95 h30
  text "S1" at -1024.99,434.95 h30
  text "CGD1200HB2P-XM3" at 649.03,401.41 h80 r90
  text "HS-OC" at 795.04,374.95 h30
  text "NTC" at 835.02,-405.05 h30
  text "G2" at -1034.99,-454.65 h30
  text "S2" at -1034.99,-645.05 h30
  text "ON" at -675,-964.95 h60
  text "OFF" at -675,-1185 h60
Bottom Overlay:
  lines w5: -200,-1400.05 -200,-1410.05 -120.42,-1418 -107.28,-1434.06 ; 10,-135.05 20,-135.05 20,-89.19 49.8,-59.38 ; 40,-1500.05 70,-1490.05 ; 135,-1315.05 155,-1335.05 ; 517.09,1336.09 532.24,1322.44
Board Shape:
  lines w3.94: -1043.31,-1474.8 ccw(c-943.31,-1474.8) -943.31,-1574.8 943.31,-1574.8 ccw(c943.31,-1474.8) 1043.31,-1474.8 1043.31,1474.8 ccw(c943.31,1474.8) 943.31,1574.8 0,1574.8 -943.31,1574.8 ccw(c-943.31,1474.8) -1043.31,1474.8 -1043.31,0 -1043.31,-1474.8
Drill Drawing:
  circle w10: c-824.38,2509.79 r33.33
  lines w10: -857.71,2043.12 -841.05,2043.12 -841.05,2026.45 -807.71,2026.45 -807.71,2043.12 -791.05,2043.12 -791.05,2076.45 -807.71,2076.45 -807.71,2093.12 -841.05,2093.12 -841.05,2076.45 -857.71,2076.45 -857.71,2043.12 ; -857.71,2176.45 -824.38,2193.12 -791.05,2176.45 -807.71,2209.79 -791.05,2243.12 -824.38,2226.45 -857.71,2243.12 -841.05,2209.79 -857.71,2176.45 ; -857.71,2326.45 -791.05,2326.45 -791.05,2393.12 -857.71,2393.12 -857.71,2326.45 ; -857.71,2693.12 -791.05,2693.12 -824.38,2626.45 -857.71,2693.12
  lines w15: -917.5,1981.45 5972.64,1981.45 ; -917.5,2731.45 5972.64,2731.45 ; -366.63,1831.45 -366.63,2881.45 ; 233.21,1831.45 233.21,2881.45 ; 1382.88,1831.45 1382.88,2881.45 ; 1888.75,1831.45 1888.75,2881.45 ; 2622.55,1831.45 2622.55,2881.45 ; 3812.21,1831.45 3812.21,2881.45 ; 4402.06,1831.45 4402.06,2881.45 ; 5147.86,1831.45 5147.86,2881.45 ; -917.5,1831.45 5972.64,1831.45 5972.64,2881.45 -917.5,2881.45 -917.5,1831.45
  text "Symbol" at -827.5,2776.45 h72
  text "Count" at -321.63,2776.45 h72
  text "Hole Size" at 278.21,2776.45 h72
  text "Plated" at 1427.88,2776.45 h72
  text "Hole Type" at 1933.75,2776.45 h72
  text "Drill Layer Pair" at 2667.55,2776.45 h72
  text "Via/Pad" at 3857.21,2776.45 h72
  text "Pad Shape" at 4447.06,2776.45 h72
  text "Template" at 5192.86,2776.45 h72
  text "419" at -321.63,2626.45 h60
  text "12.99mil (0.330mm)" at 278.21,2626.45 h60
  text "PTH" at 1427.88,2626.45 h60
  text "Round" at 1933.75,2626.45 h60
  text "TOP - BOTTOM" at 2667.55,2626.45 h60
  text "Via" at 3857.21,2626.45 h60
  text "Rounded" at 4447.06,2626.45 h60
  text "(Mixed)" at 5192.86,2626.45 h60
  text "10" at -321.63,2476.45 h60
  text "33.07mil (0.840mm)" at 278.21,2476.45 h60
  text "PTH" at 1427.88,2476.45 h60
  text "Round" at 1933.75,2476.45 h60
  text "TOP - BOTTOM" at 2667.55,2476.45 h60
  text "Pad" at 3857.21,2476.45 h60
  text "Rounded" at 4447.06,2476.45 h60
  text "(Mixed)" at 5192.86,2476.45 h60
  text "16" at -321.63,2326.45 h60
  text "40.00mil (1.016mm)" at 278.21,2326.45 h60
  text "PTH" at 1427.88,2326.45 h60
  text "Round" at 1933.75,2326.45 h60
  text "TOP - BOTTOM" at 2667.55,2326.45 h60
  text "Pad" at 3857.21,2326.45 h60
  text "Rounded" at 4447.06,2326.45 h60
  text "c152h102m163" at 5192.86,2326.45 h60
  text "10" at -321.63,2176.45 h60
  text "45.28mil (1.150mm)" at 278.21,2176.45 h60
  text "PTH" at 1427.88,2176.45 h60
  text "Round" at 1933.75,2176.45 h60
  text "TOP - BOTTOM" at 2667.55,2176.45 h60
  text "Pad" at 3857.21,2176.45 h60
  text "(Mixed)" at 4447.06,2176.45 h60
  text "(Mixed)" at 5192.86,2176.45 h60
  text "4" at -321.63,2026.45 h60
  text "175.00mil (4.445mm)" at 278.21,2026.45 h60
  text "NPTH" at 1427.88,2026.45 h60
  text "Round" at 1933.75,2026.45 h60
  text "TOP - BOTTOM" at 2667.55,2026.45 h60
  text "Pad" at 3857.21,2026.45 h60
  text "Rounded" at 4447.06,2026.45 h60
  text "c0hn444" at 5192.86,2026.45 h60
  text "459 Total" at -321.63,1876.45 h60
